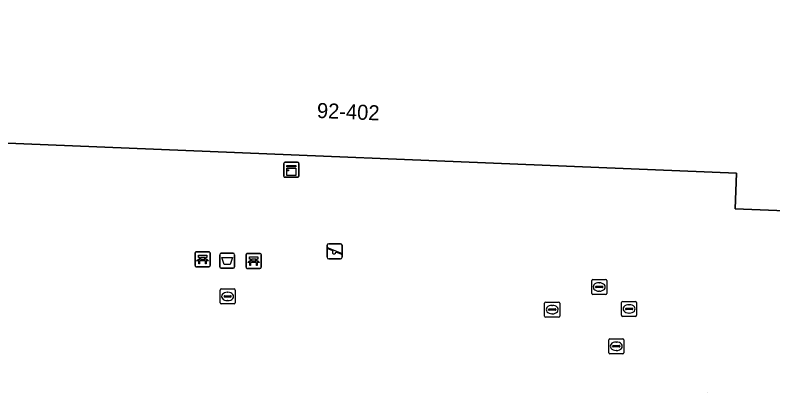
# Model space of a CAD drawing. Extents: x 160888 to 161385, y 386490 to 386908.
# Drawn here: x 161090.9 to 161141.4, y 386712.7 to 386737.3 of the extents above; entities that cross this region are included whole.
import ezdxf

# ---------------------------------------------------------------- set-up
doc = ezdxf.new("R2010")
doc.units = 0
for name, color, linetype in [('IMGEO_Afvalbak', 7, 'Continuous'), ('IMGEO_Bank', 7, 'Continuous'), ('IMGEO_Brandkraan', 7, 'Continuous'), ('IMGEO_Kast', 7, 'Continuous'), ('IMGEO_Kolk', 7, 'Continuous'), ('IMGEO_Pand', 7, 'Continuous'), ('IMGEO_Pand_nummerreeks', 7, 'Continuous'), ('IMGEO_Rioolput', 7, 'Continuous'), ('IMGEO_Speelvoorziening', 7, 'Continuous'), ('IMGEO_Voetgangersgebied_open', 7, 'Continuous')]:
    doc.layers.add(name, color=color, linetype=linetype)

msp = doc.modelspace()

# ---------------------------------------------------------------- linework, layer by layer
at = {"layer": 'IMGEO_Afvalbak'}
for p, q in [((161104.659, 386721.482), (161105.449, 386721.482)), ((161105.449, 386721.482), (161104.659, 386721.482)), ((161104.559, 386720.582), (161104.559, 386721.382)), ((161104.559, 386721.382), (161104.559, 386720.582)), ((161105.549, 386721.382), (161105.549, 386720.582)), ((161105.549, 386720.582), (161105.549, 386721.382)), ((161105.449, 386720.482), (161104.659, 386720.482)), ((161104.659, 386720.482), (161105.449, 386720.482))]:
    msp.add_line(p, q, dxfattribs=at)
msp.add_lwpolyline([(161104.702, 386721.196), (161105.406, 386721.196), (161105.257, 386720.726), (161104.851, 386720.726), (161104.702, 386721.196)], dxfattribs=at)
for centre, start, end in [((161104.659, 386721.382), 90, 180), ((161104.659, 386721.382), 90, 180), ((161105.449, 386721.382), 0, 90), ((161105.449, 386721.382), 360, 90), ((161104.659, 386720.582), 180, 270), ((161104.659, 386720.582), 180, 270), ((161105.449, 386720.582), 270, 0), ((161105.449, 386720.582), 270, 0)]:
    msp.add_arc(centre, 0.1, start, end, dxfattribs=at)
at = {"layer": 'IMGEO_Bank'}
for p, q in [((161102.921, 386720.656), (161102.921, 386721.497)), ((161102.921, 386721.497), (161102.921, 386720.656)), ((161102.996, 386721.581), (161103.837, 386721.581)), ((161103.837, 386721.581), (161102.996, 386721.581)), ((161103.921, 386721.506), (161103.921, 386720.665)), ((161103.921, 386720.665), (161103.921, 386721.506)), ((161106.393, 386721.469), (161107.234, 386721.469)), ((161107.234, 386721.469), (161106.393, 386721.469)), ((161103.618, 386720.979), (161103.225, 386720.979)), ((161103.23, 386721.087), (161103.23, 386721.193)), ((161103.274, 386721.193), (161103.274, 386721.087)), ((161103.562, 386721.199), (161103.28, 386721.199)), ((161103.28, 386721.081), (161103.562, 386721.081)), ((161103.568, 386721.087), (161103.568, 386721.193)), ((161103.612, 386721.193), (161103.612, 386721.087)), ((161106.318, 386720.544), (161106.318, 386721.385)), ((161106.318, 386721.385), (161106.318, 386720.544)), ((161106.627, 386720.975), (161106.627, 386721.081)), ((161106.671, 386721.081), (161106.671, 386720.975)), ((161106.959, 386721.087), (161106.677, 386721.087)), ((161106.677, 386720.969), (161106.959, 386720.969)), ((161106.965, 386720.975), (161106.965, 386721.081)), ((161107.009, 386721.081), (161107.009, 386720.975)), ((161107.318, 386721.394), (161107.318, 386720.553)), ((161107.318, 386720.553), (161107.318, 386721.394)), ((161103.846, 386720.581), (161103.005, 386720.581)), ((161103.005, 386720.581), (161103.846, 386720.581)), ((161107.243, 386720.469), (161106.402, 386720.469)), ((161106.402, 386720.469), (161107.243, 386720.469)), ((161107.015, 386720.867), (161106.622, 386720.867))]:
    msp.add_line(p, q, dxfattribs=at)
for points in [[(161103.168, 386720.979), (161103.026, 386720.979), (161103.138, 386721.081), (161103.224, 386721.081)], [(161103.224, 386721.199), (161103.138, 386721.199), (161103.138, 386721.36), (161103.701, 386721.36), (161103.701, 386721.199), (161103.618, 386721.199)], [(161103.218, 386720.972), (161103.218, 386720.765), (161103.175, 386720.765), (161103.175, 386720.972)], [(161103.618, 386721.081), (161103.701, 386721.081), (161103.813, 386720.979), (161103.674, 386720.979)], [(161103.668, 386720.972), (161103.668, 386720.765), (161103.624, 386720.765), (161103.624, 386720.972)], [(161106.565, 386720.867), (161106.423, 386720.867), (161106.535, 386720.969), (161106.621, 386720.969)], [(161106.621, 386721.087), (161106.535, 386721.087), (161106.535, 386721.248), (161107.098, 386721.248), (161107.098, 386721.087), (161107.015, 386721.087)], [(161107.015, 386720.969), (161107.098, 386720.969), (161107.21, 386720.867), (161107.071, 386720.867)], [(161106.615, 386720.86), (161106.615, 386720.653), (161106.572, 386720.653), (161106.572, 386720.86)], [(161107.065, 386720.86), (161107.065, 386720.653), (161107.021, 386720.653), (161107.021, 386720.86)]]:
    msp.add_lwpolyline(points, dxfattribs=at)
for centre, radius, start, end in [((161102.999, 386721.503), 0.0779, 92.4484, 184.2845), ((161102.999, 386721.503), 0.0779, 92.4484, 184.2845), ((161103.843, 386721.503), 0.0779, 2.4484, 94.2845), ((161103.843, 386721.503), 0.0779, 2.4484, 94.2845), ((161106.396, 386721.391), 0.0779, 92.4484, 184.2845), ((161106.396, 386721.391), 0.0779, 92.4484, 184.2845), ((161107.24, 386721.391), 0.0779, 2.4484, 94.2845), ((161107.24, 386721.391), 0.0779, 2.4484, 94.2845), ((161103.168, 386720.972), 0.00671, 2.8957, 87.1043), ((161103.225, 386720.972), 0.00671, 92.8957, 177.1043), ((161103.223, 386721.192), 0.00671, 2.8957, 87.1043), ((161103.223, 386721.088), 0.00671, 272.8957, 357.1043), ((161103.28, 386721.192), 0.00671, 92.8957, 177.1043), ((161103.28, 386721.088), 0.00671, 182.8957, 267.1043), ((161103.562, 386721.192), 0.00671, 2.8957, 87.1043), ((161103.562, 386721.088), 0.00671, 272.8957, 357.1043), ((161103.619, 386721.192), 0.00671, 92.8957, 177.1043), ((161103.619, 386721.088), 0.00671, 182.8957, 267.1043), ((161103.617, 386720.972), 0.00671, 2.8957, 87.1043), ((161103.674, 386720.972), 0.00671, 92.8957, 177.1043), ((161106.62, 386721.08), 0.00671, 2.8957, 87.1043), ((161106.62, 386720.976), 0.00671, 272.8957, 357.1043), ((161106.677, 386721.08), 0.00671, 92.8957, 177.1043), ((161106.677, 386720.976), 0.00671, 182.8957, 267.1043), ((161106.959, 386721.08), 0.00671, 2.8957, 87.1043), ((161106.959, 386720.976), 0.00671, 272.8957, 357.1043), ((161107.016, 386721.08), 0.00671, 92.8957, 177.1043), ((161107.016, 386720.976), 0.00671, 182.8957, 267.1043), ((161102.999, 386720.659), 0.0779, 182.4484, 274.2845), ((161102.999, 386720.659), 0.0779, 182.4484, 274.2845), ((161103.843, 386720.659), 0.0779, 272.4484, 4.2845), ((161103.843, 386720.659), 0.0779, 272.4484, 4.2845), ((161106.396, 386720.547), 0.0779, 182.4484, 274.2845), ((161106.396, 386720.547), 0.0779, 182.4484, 274.2845), ((161106.565, 386720.86), 0.00671, 2.8957, 87.1043), ((161106.622, 386720.86), 0.00671, 92.8957, 177.1043), ((161107.014, 386720.86), 0.00671, 2.8957, 87.1043), ((161107.071, 386720.86), 0.00671, 92.8957, 177.1043), ((161107.24, 386720.547), 0.0779, 272.4484, 4.2845), ((161107.24, 386720.547), 0.0779, 272.4484, 4.2845)]:
    msp.add_arc(centre, radius, start, end, dxfattribs=at)
at = {"layer": 'IMGEO_Brandkraan'}
for p, q in [((161130.468, 386714.863), (161130.468, 386715.715)), ((161130.543, 386715.789), (161131.395, 386715.789)), ((161130.956, 386715.569), (161130.981, 386715.569)), ((161131.469, 386715.715), (161131.469, 386714.863)), ((161130.727, 386715.283), (161130.727, 386715.295)), ((161131.165, 386715.246), (161130.767, 386715.246)), ((161130.77, 386715.332), (161131.168, 386715.332)), ((161130.979, 386715.009), (161130.954, 386715.009)), ((161131.211, 386715.295), (161131.211, 386715.283)), ((161131.395, 386714.789), (161130.543, 386714.789))]:
    msp.add_line(p, q, dxfattribs=at)
for points in [[(161130.468, 386714.863), (161130.468, 386715.715)], [(161130.543, 386715.789), (161131.395, 386715.789)], [(161131.469, 386715.715), (161131.469, 386714.863)], [(161131.395, 386714.789), (161130.543, 386714.789)]]:
    msp.add_lwpolyline(points, dxfattribs=at)
for centre, radius, start, end in [((161130.545, 386715.713), 0.0765, 91.552, 178.448), ((161130.545, 386715.713), 0.0765, 91.552, 178.448), ((161131.393, 386715.713), 0.0765, 1.552, 88.448), ((161131.393, 386715.713), 0.0765, 1.552, 88.448), ((161130.545, 386714.865), 0.0765, 181.552, 268.448), ((161130.545, 386714.865), 0.0765, 181.552, 268.448), ((161130.767, 386715.292), 0.0403, 85.8775, 175.7526), ((161130.764, 386715.282), 0.0366, 178.938, 274.7102), ((161131.168, 386715.289), 0.043, 264.8664, 352.4533), ((161131.172, 386715.294), 0.0386, 1.7309, 96.639), ((161131.393, 386714.865), 0.0765, 271.552, 358.448), ((161131.393, 386714.865), 0.0765, 271.552, 358.448)]:
    msp.add_arc(centre, radius, start, end, dxfattribs=at)
for centre, major_axis, ratio, start_param, end_param in [((161130.955, 386715.289), (-0.387, 0.002), 0.722429, 4.712389, 7.853982), ((161130.98, 386715.289), (-0.39, 0.002), 0.717154, 1.570796, 4.712389)]:
    msp.add_ellipse(centre, major_axis=major_axis, ratio=ratio, start_param=start_param, end_param=end_param, dxfattribs=at)
at = {"layer": 'IMGEO_Kast'}
for p, q in [((161108.903, 386727.531), (161109.744, 386727.531)), ((161109.744, 386727.531), (161108.903, 386727.531)), ((161108.828, 386726.606), (161108.828, 386727.447)), ((161108.828, 386727.447), (161108.828, 386726.606)), ((161109.828, 386727.456), (161109.828, 386726.615)), ((161109.828, 386726.615), (161109.828, 386727.456)), ((161109.753, 386726.531), (161108.912, 386726.531)), ((161108.912, 386726.531), (161109.753, 386726.531))]:
    msp.add_line(p, q, dxfattribs=at)
for points in [[(161109.023, 386727.321), (161109.623, 386727.321), (161109.623, 386727.236), (161109.023, 386727.236), (161109.023, 386727.321)], [(161109.023, 386727.146), (161109.623, 386727.146), (161109.623, 386726.657), (161109.023, 386726.657), (161109.023, 386727.146)]]:
    msp.add_lwpolyline(points, dxfattribs=at)
msp.add_circle((161109.107, 386726.995), 0.0377, dxfattribs=at)
for centre, start, end in [((161108.906, 386727.453), 92.4484, 184.2845), ((161108.906, 386727.453), 92.4484, 184.2845), ((161109.75, 386727.453), 2.4484, 94.2845), ((161109.75, 386727.453), 2.4484, 94.2845), ((161108.906, 386726.609), 182.4484, 274.2845), ((161108.906, 386726.609), 182.4484, 274.2845), ((161109.75, 386726.609), 272.4484, 4.2845), ((161109.75, 386726.609), 272.4484, 4.2845)]:
    msp.add_arc(centre, 0.0779, start, end, dxfattribs=at)
at = {"layer": 'IMGEO_Kolk'}
for p, q in [((161104.588, 386718.179), (161104.588, 386719.031)), ((161104.663, 386719.105), (161105.515, 386719.105)), ((161105.589, 386719.031), (161105.589, 386718.179)), ((161104.847, 386718.599), (161104.847, 386718.611)), ((161105.285, 386718.562), (161104.887, 386718.562)), ((161104.89, 386718.648), (161105.288, 386718.648)), ((161105.076, 386718.885), (161105.101, 386718.885)), ((161105.331, 386718.611), (161105.331, 386718.599)), ((161105.515, 386718.105), (161104.663, 386718.105)), ((161105.099, 386718.325), (161105.074, 386718.325)), ((161126.199, 386717.303), (161126.199, 386718.155)), ((161126.274, 386718.229), (161127.126, 386718.229)), ((161126.687, 386718.009), (161126.712, 386718.009)), ((161127.2, 386718.155), (161127.2, 386717.303)), ((161126.458, 386717.723), (161126.458, 386717.735)), ((161126.896, 386717.686), (161126.498, 386717.686)), ((161126.501, 386717.772), (161126.899, 386717.772)), ((161126.71, 386717.449), (161126.685, 386717.449)), ((161126.942, 386717.735), (161126.942, 386717.723)), ((161127.126, 386717.229), (161126.274, 386717.229))]:
    msp.add_line(p, q, dxfattribs=at)
for points in [[(161104.588, 386718.179), (161104.588, 386719.031)], [(161104.663, 386719.105), (161105.515, 386719.105)], [(161105.589, 386719.031), (161105.589, 386718.179)], [(161105.515, 386718.105), (161104.663, 386718.105)], [(161126.199, 386717.303), (161126.199, 386718.155)], [(161126.274, 386718.229), (161127.126, 386718.229)], [(161127.2, 386718.155), (161127.2, 386717.303)], [(161127.126, 386717.229), (161126.274, 386717.229)]]:
    msp.add_lwpolyline(points, dxfattribs=at)
for centre, radius, start, end in [((161104.665, 386719.029), 0.0765, 91.552, 178.448), ((161104.665, 386719.029), 0.0765, 91.552, 178.448), ((161105.513, 386719.029), 0.0765, 1.552, 88.448), ((161105.513, 386719.029), 0.0765, 1.552, 88.448), ((161104.887, 386718.608), 0.0403, 85.8775, 175.7526), ((161104.884, 386718.598), 0.0366, 178.938, 274.7102), ((161105.288, 386718.605), 0.043, 264.8664, 352.4533), ((161105.292, 386718.61), 0.0386, 1.7309, 96.639), ((161104.665, 386718.181), 0.0765, 181.552, 268.448), ((161104.665, 386718.181), 0.0765, 181.552, 268.448), ((161105.513, 386718.181), 0.0765, 271.552, 358.448), ((161105.513, 386718.181), 0.0765, 271.552, 358.448), ((161126.276, 386718.153), 0.0765, 91.552, 178.448), ((161126.276, 386718.153), 0.0765, 91.552, 178.448), ((161127.124, 386718.153), 0.0765, 1.552, 88.448), ((161127.124, 386718.153), 0.0765, 1.552, 88.448), ((161126.498, 386717.732), 0.0403, 85.8775, 175.7526), ((161126.495, 386717.722), 0.0366, 178.938, 274.7102), ((161126.899, 386717.729), 0.043, 264.8664, 352.4533), ((161126.903, 386717.734), 0.0386, 1.7309, 96.639), ((161126.276, 386717.305), 0.0765, 181.552, 268.448), ((161126.276, 386717.305), 0.0765, 181.552, 268.448), ((161127.124, 386717.305), 0.0765, 271.552, 358.448), ((161127.124, 386717.305), 0.0765, 271.552, 358.448)]:
    msp.add_arc(centre, radius, start, end, dxfattribs=at)
for centre, major_axis, ratio, start_param, end_param in [((161105.075, 386718.605), (-0.387, 0.002), 0.722429, 4.712389, 7.853982), ((161105.1, 386718.605), (-0.39, 0.002), 0.717154, 1.570796, 4.712389), ((161126.686, 386717.729), (-0.387, 0.002), 0.722429, 4.712389, 7.853982), ((161126.711, 386717.729), (-0.39, 0.002), 0.717154, 1.570796, 4.712389)]:
    msp.add_ellipse(centre, major_axis=major_axis, ratio=ratio, start_param=start_param, end_param=end_param, dxfattribs=at)
at = {"layer": 'IMGEO_Pand'}
msp.add_lwpolyline([(161162.623, 386750), (161162.813, 386754.694), (161158.078, 386754.881), (161138.515, 386755.653), (161136.481, 386755.736), (161090.937, 386757.602), (161090.349, 386743.254), (161088.151, 386743.344), (161088.742, 386757.7), (161068.761, 386758.511), (161068.579, 386753.93), (161068.422, 386750), (161067.82, 386734.914), (161068.128, 386734.901), (161081.411, 386726.666), (161089.223, 386726.344), (161089.335, 386728.855), (161138.981, 386726.813), (161138.885, 386724.445), (161161.551, 386723.521)], close=True, dxfattribs=at)
at = {"layer": 'IMGEO_Rioolput'}
for p, q in [((161129.33, 386718.809), (161129.33, 386719.661)), ((161129.405, 386719.735), (161130.257, 386719.735)), ((161129.818, 386719.515), (161129.843, 386719.515)), ((161130.331, 386719.661), (161130.331, 386718.809)), ((161129.589, 386719.229), (161129.589, 386719.241)), ((161130.027, 386719.192), (161129.629, 386719.192)), ((161129.632, 386719.278), (161130.03, 386719.278)), ((161129.841, 386718.955), (161129.816, 386718.955)), ((161130.073, 386719.241), (161130.073, 386719.229)), ((161130.257, 386718.735), (161129.405, 386718.735)), ((161131.322, 386717.351), (161131.322, 386718.203)), ((161131.397, 386718.277), (161132.249, 386718.277)), ((161131.81, 386718.057), (161131.835, 386718.057)), ((161132.323, 386718.203), (161132.323, 386717.351)), ((161131.581, 386717.771), (161131.581, 386717.783)), ((161132.019, 386717.734), (161131.621, 386717.734)), ((161131.624, 386717.82), (161132.022, 386717.82)), ((161131.833, 386717.497), (161131.808, 386717.497)), ((161132.065, 386717.783), (161132.065, 386717.771)), ((161132.249, 386717.277), (161131.397, 386717.277))]:
    msp.add_line(p, q, dxfattribs=at)
for points in [[(161129.33, 386718.809), (161129.33, 386719.661)], [(161129.405, 386719.735), (161130.257, 386719.735)], [(161130.331, 386719.661), (161130.331, 386718.809)], [(161130.257, 386718.735), (161129.405, 386718.735)], [(161131.322, 386717.351), (161131.322, 386718.203)], [(161131.397, 386718.277), (161132.249, 386718.277)], [(161132.323, 386718.203), (161132.323, 386717.351)], [(161132.249, 386717.277), (161131.397, 386717.277)]]:
    msp.add_lwpolyline(points, dxfattribs=at)
for centre, radius, start, end in [((161129.407, 386719.659), 0.0765, 91.552, 178.448), ((161129.407, 386719.659), 0.0765, 91.552, 178.448), ((161130.255, 386719.659), 0.0765, 1.552, 88.448), ((161130.255, 386719.659), 0.0765, 1.552, 88.448), ((161129.629, 386719.238), 0.0403, 85.8775, 175.7526), ((161129.626, 386719.228), 0.0366, 178.938, 274.7102), ((161130.03, 386719.235), 0.043, 264.8664, 352.4533), ((161130.034, 386719.24), 0.0386, 1.7309, 96.639), ((161129.407, 386718.811), 0.0765, 181.552, 268.448), ((161129.407, 386718.811), 0.0765, 181.552, 268.448), ((161130.255, 386718.811), 0.0765, 271.552, 358.448), ((161130.255, 386718.811), 0.0765, 271.552, 358.448), ((161131.399, 386718.201), 0.0765, 91.552, 178.448), ((161131.399, 386718.201), 0.0765, 91.552, 178.448), ((161132.247, 386718.201), 0.0765, 1.552, 88.448), ((161132.247, 386718.201), 0.0765, 1.552, 88.448), ((161131.621, 386717.78), 0.0403, 85.8775, 175.7526), ((161131.618, 386717.77), 0.0366, 178.938, 274.7102), ((161132.022, 386717.777), 0.043, 264.8664, 352.4533), ((161132.026, 386717.782), 0.0386, 1.7309, 96.639), ((161131.399, 386717.353), 0.0765, 181.552, 268.448), ((161131.399, 386717.353), 0.0765, 181.552, 268.448), ((161132.247, 386717.353), 0.0765, 271.552, 358.448), ((161132.247, 386717.353), 0.0765, 271.552, 358.448)]:
    msp.add_arc(centre, radius, start, end, dxfattribs=at)
for centre, major_axis, ratio, start_param, end_param in [((161129.817, 386719.235), (-0.387, 0.002), 0.722429, 4.712389, 7.853982), ((161129.842, 386719.235), (-0.39, 0.002), 0.717154, 1.570796, 4.712389), ((161131.809, 386717.777), (-0.387, 0.002), 0.722429, 4.712389, 7.853982), ((161131.834, 386717.777), (-0.39, 0.002), 0.717154, 1.570796, 4.712389)]:
    msp.add_ellipse(centre, major_axis=major_axis, ratio=ratio, start_param=start_param, end_param=end_param, dxfattribs=at)
at = {"layer": 'IMGEO_Speelvoorziening'}
for p, q in [((161111.718, 386721.21), (161111.718, 386722.01)), ((161111.718, 386722.01), (161111.718, 386721.21)), ((161111.818, 386722.11), (161112.608, 386722.11)), ((161112.608, 386722.11), (161111.818, 386722.11)), ((161112.708, 386722.01), (161112.708, 386721.21)), ((161112.708, 386721.21), (161112.708, 386722.01)), ((161112.101, 386721.638), (161111.762, 386721.775)), ((161111.787, 386721.835), (161112.663, 386721.482)), ((161112.639, 386721.422), (161112.299, 386721.559)), ((161112.608, 386721.11), (161111.818, 386721.11)), ((161111.818, 386721.11), (161112.608, 386721.11))]:
    msp.add_line(p, q, dxfattribs=at)
for centre, radius, start, end in [((161111.818, 386722.01), 0.1, 90, 180), ((161111.818, 386722.01), 0.1, 90, 180), ((161112.608, 386722.01), 0.1, 0, 90), ((161112.608, 386722.01), 0.1, 360, 90), ((161111.775, 386721.805), 0.0327, 68.078, 248.078), ((161112.18, 386721.548), 0.12, 130.9928, 5.1632), ((161112.651, 386721.452), 0.0327, 248.078, 68.078), ((161111.818, 386721.21), 0.1, 180, 270), ((161111.818, 386721.21), 0.1, 180, 270), ((161112.608, 386721.21), 0.1, 270, 0), ((161112.608, 386721.21), 0.1, 270, 0)]:
    msp.add_arc(centre, radius, start, end, dxfattribs=at)
at = {"layer": 'IMGEO_Voetgangersgebied_open'}
msp.add_lwpolyline([(161161.551, 386723.521), (161138.885, 386724.445), (161138.981, 386726.813), (161089.335, 386728.855), (161089.223, 386726.344), (161081.411, 386726.666), (161068.128, 386734.901), (161067.82, 386734.914), (161066.624, 386705.366), (161066.929, 386705.356), (161080.851, 386712.475), (161127.462, 386710.495), (161136.985, 386710.09), (161137.065, 386712.159), (161147.892, 386711.738)], dxfattribs=at)

# ---------------------------------------------------------------- texts
at = {"layer": 'IMGEO_Pand_nummerreeks'}
msp.add_text('92-402', height=1, rotation=357.6451, dxfattribs=at).set_placement((161111.019, 386730.485))

doc.saveas('drawing.dxf')
